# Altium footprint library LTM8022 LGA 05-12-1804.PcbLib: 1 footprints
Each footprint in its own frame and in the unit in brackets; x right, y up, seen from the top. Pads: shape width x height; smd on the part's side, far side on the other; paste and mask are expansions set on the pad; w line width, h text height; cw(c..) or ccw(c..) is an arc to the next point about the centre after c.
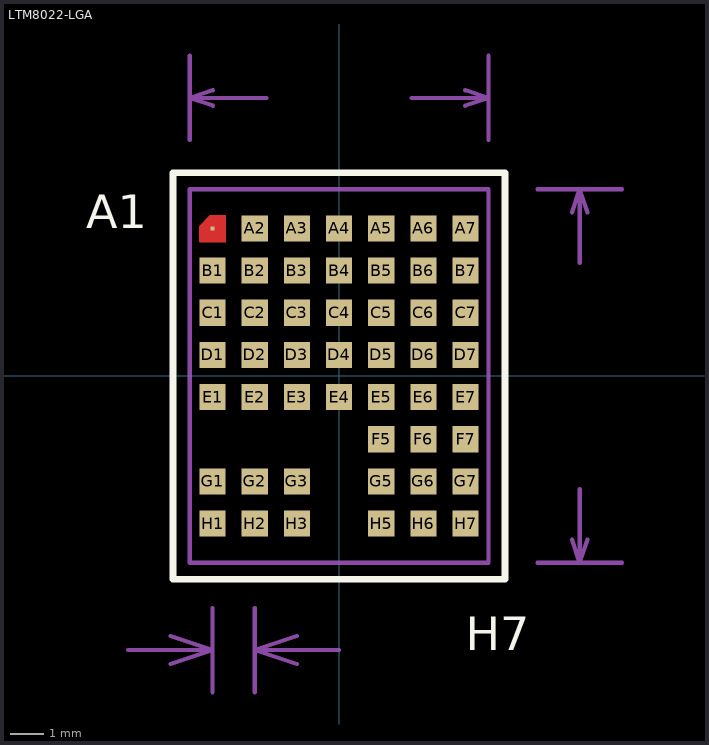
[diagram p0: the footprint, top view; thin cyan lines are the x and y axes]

## LTM8022-LGA [mil]
pads (50):
  rect 5x5 smd paste-3.5 mask-3: A1(-150,175)
  rect 31x31 smd paste-3.5 mask-3: A2(-100,175) A3(-50,175) A4(0,175) A5(50,175) A6(100,175) A7(150,175) B1(-150,125) B2(-100,125) B3(-50,125) B4(0,125) B5(50,125) B6(100,125) B7(150,125) C1(-150,75) C2(-100,75) C3(-50,75) C4(0,75) C5(50,75) C6(100,75) C7(150,75) D1(-150,25) D2(-100,25) D3(-50,25) D4(0,25) D5(50,25) D6(100,25) D7(150,25) E1(-150,-25) E2(-100,-25) E3(-50,-25) E4(0,-25) E5(50,-25) E6(100,-25) E7(150,-25) F5(50,-75) F6(100,-75) F7(150,-75) G1(-150,-125) G2(-100,-125) G3(-50,-125) G5(50,-125) G6(100,-125) G7(150,-125) H1(-150,-175) H2(-100,-175) H3(-50,-175) H5(50,-175) H6(100,-175) H7(150,-175)
TopLayer:
  region: -165.5,159.5 -134.5,159.5 -134.5,190.5 -152.5,190.5 -165.5,177.5
  lines w0.39: -165.5,159.5 -165.5,177.5 -152.5,190.5 -134.5,190.5 -134.5,159.5 -165.5,159.5
TopOverlay:
  lines w8: -196.85,-241.14 -196.85,241.14 196.85,241.14 196.85,-241.14 -196.85,-241.14
  text "H7" at 150,-325 h40
  text "A1" at -300,175 h40
Mechanical16:
  lines w5: -250,-325 -150,-325 ; -200,-341.67 -150,-325 ; -200,-308.33 -150,-325 ; -177.17,279.72 -177.17,379.72 ; -150,-375 -150,-275 ; -149.61,320.54 -177.17,329.72 ; -149.61,338.91 -177.17,329.72 ; -100,-375 -100,-275 ; -86.17,329.72 -177.17,329.72 ; -50,-341.67 -100,-325 ; -50,-308.33 -100,-325 ; 0,-325 -100,-325 ; 86.17,329.72 177.17,329.72 ; 149.61,320.54 177.17,329.72 ; 149.61,338.91 177.17,329.72 ; 177.17,279.72 177.17,379.72 ; 235.43,-221.46 335.43,-221.46 ; 235.43,221.46 335.43,221.46 ; 276.25,-193.9 285.43,-221.46 ; 276.25,193.9 285.43,221.46 ; 285.43,-134.38 285.43,-221.46 ; 285.43,134.38 285.43,221.46 ; 294.62,-193.9 285.43,-221.46 ; 294.62,193.9 285.43,221.46 ; -177.17,-221.46 177.17,-221.46 177.17,221.46 -177.17,221.46 -177.17,-221.46
  text "1.27 (mm)" at -325.77,-444.97 h50
  text "11.25 (mm)" at 304.21,-124.38 h27.56
  text "9 (mm)" at -76.17,310.95 h27.56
